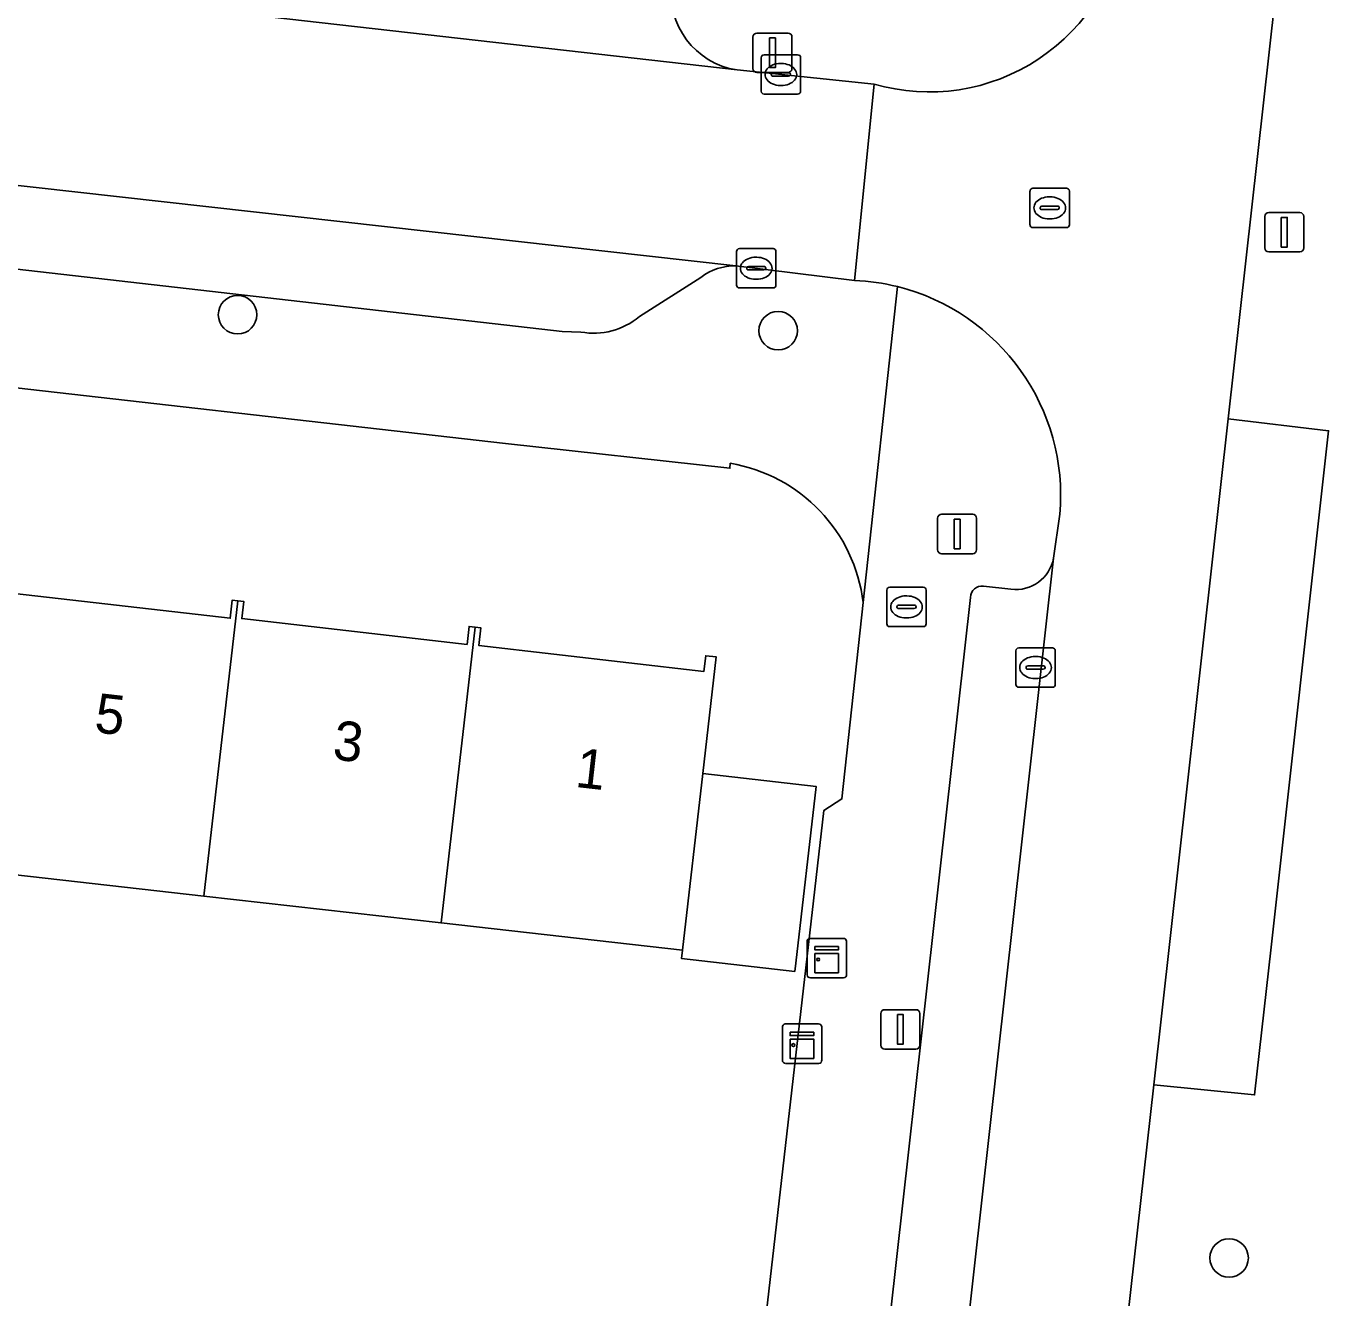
# Model space of a CAD drawing. Extents: x 161928 to 163071, y 386474 to 387428.
# Drawn here: x 162156.16 to 162189.6, y 386612.39 to 386644.64 of the extents above; entities that cross this region are included whole.
import ezdxf

# ---------------------------------------------------------------- set-up
doc = ezdxf.new("R2010")
doc.units = 0
for name, color, linetype in [('IMGEO_Berm_groen', 7, 'Continuous'), ('IMGEO_Boom', 7, 'Continuous'), ('IMGEO_Brandkraan', 7, 'Continuous'), ('IMGEO_Erf', 7, 'Continuous'), ('IMGEO_Kast', 7, 'Continuous'), ('IMGEO_Kolk', 7, 'Continuous'), ('IMGEO_Lichtmast', 7, 'Continuous'), ('IMGEO_Pand', 7, 'Continuous'), ('IMGEO_Pand_nummerreeks', 7, 'Continuous'), ('IMGEO_Parkeervlak_open', 7, 'Continuous'), ('IMGEO_Rijbaan_lokaal_open', 7, 'Continuous'), ('IMGEO_Rioolput', 7, 'Continuous'), ('IMGEO_Voetpad_open', 7, 'Continuous')]:
    doc.layers.add(name, color=color, linetype=linetype)

msp = doc.modelspace()

# ---------------------------------------------------------------- linework, layer by layer
at = {"layer": 'IMGEO_Berm_groen'}
msp.add_lwpolyline([(162189.709, 386662.217), (162189.32, 386658.663), (162186.639, 386634.684), (162189.19, 386634.379), (162187.73, 386621.281), (162187.312, 386617.53), (162184.757, 386617.783), (162181.174, 386585.88)], dxfattribs=at)
at = {"layer": 'IMGEO_Boom'}
for centre in [(162161.515, 386637.324), (162175.227, 386636.918), (162186.666, 386613.392)]:
    msp.add_circle(centre, 0.489, dxfattribs=at)
at = {"layer": 'IMGEO_Brandkraan'}
for p, q in [((162177.982, 386629.484), (162177.982, 386630.336)), ((162178.057, 386630.41), (162178.909, 386630.41)), ((162178.983, 386630.336), (162178.983, 386629.484)), ((162178.47, 386630.19), (162178.495, 386630.19)), ((162178.241, 386629.904), (162178.241, 386629.916)), ((162178.679, 386629.867), (162178.281, 386629.867)), ((162178.284, 386629.953), (162178.682, 386629.953)), ((162178.725, 386629.916), (162178.725, 386629.904)), ((162178.909, 386629.41), (162178.057, 386629.41)), ((162178.493, 386629.63), (162178.468, 386629.63))]:
    msp.add_line(p, q, dxfattribs=at)
for points in [[(162177.982, 386629.484), (162177.982, 386630.336)], [(162178.057, 386630.41), (162178.909, 386630.41)], [(162178.983, 386630.336), (162178.983, 386629.484)], [(162178.909, 386629.41), (162178.057, 386629.41)]]:
    msp.add_lwpolyline(points, dxfattribs=at)
for centre, radius, start, end in [((162178.059, 386630.334), 0.0765, 91.552, 178.448), ((162178.059, 386630.334), 0.0765, 91.552, 178.448), ((162178.907, 386630.334), 0.0765, 1.552, 88.448), ((162178.907, 386630.334), 0.0765, 1.552, 88.448), ((162178.281, 386629.913), 0.0403, 85.8775, 175.7526), ((162178.278, 386629.903), 0.0366, 178.938, 274.7102), ((162178.682, 386629.91), 0.043, 264.8664, 352.4533), ((162178.686, 386629.915), 0.0386, 1.7309, 96.639), ((162178.059, 386629.486), 0.0765, 181.552, 268.448), ((162178.059, 386629.486), 0.0765, 181.552, 268.448), ((162178.907, 386629.486), 0.0765, 271.552, 358.448), ((162178.907, 386629.486), 0.0765, 271.552, 358.448)]:
    msp.add_arc(centre, radius, start, end, dxfattribs=at)
for centre, major_axis, ratio, start_param, end_param in [((162178.469, 386629.91), (-0.387, 0.002), 0.722429, 4.712389, 7.853982), ((162178.494, 386629.91), (-0.39, 0.002), 0.717154, 1.570796, 4.712389)]:
    msp.add_ellipse(centre, major_axis=major_axis, ratio=ratio, start_param=start_param, end_param=end_param, dxfattribs=at)
at = {"layer": 'IMGEO_Erf'}
for points in [[(162174.012, 386633.555), (162174.002, 386633.43), (162168.309, 386634.058), (162124.601, 386639.029), (162121.966, 386615.861), (162125.693, 386615.447), (162129.321, 386615.04), (162133.478, 386614.574), (162133.214, 386612.225)], [(162155.563, 386630.286), (162161.329, 386629.621), (162161.382, 386630.083), (162161.525, 386630.067), (162161.671, 386630.05), (162161.621, 386629.616), (162167.335, 386628.957), (162167.388, 386629.414), (162167.54, 386629.396), (162167.688, 386629.379), (162167.637, 386628.931), (162173.345, 386628.273), (162173.391, 386628.671), (162173.656, 386628.641), (162173.316, 386625.686), (162176.189, 386625.355), (162175.673, 386620.876), (162175.648, 386620.661), (162172.775, 386620.992), (162172.799, 386621.201), (162166.676, 386621.893), (162160.662, 386622.573), (162154.617, 386623.256)], [(162176.389, 386624.747), (162176.844, 386625.037), (162177.384, 386630.02)], [(162174.405, 386607.455), (162176.389, 386624.747)]]:
    msp.add_lwpolyline(points, dxfattribs=at)
msp.add_arc((162173.329, 386629.528), 4.084, 6.9173, 80.3789, dxfattribs=at)
at = {"layer": 'IMGEO_Kast'}
for p, q in [((162175.963, 386620.576), (162175.963, 386621.417)), ((162175.963, 386621.417), (162175.963, 386620.576)), ((162176.038, 386621.501), (162176.879, 386621.501)), ((162176.879, 386621.501), (162176.038, 386621.501)), ((162176.963, 386621.426), (162176.963, 386620.585)), ((162176.963, 386620.585), (162176.963, 386621.426)), ((162176.888, 386620.501), (162176.047, 386620.501)), ((162176.047, 386620.501), (162176.888, 386620.501)), ((162175.409, 386619.329), (162176.25, 386619.329)), ((162176.25, 386619.329), (162175.409, 386619.329)), ((162175.334, 386618.404), (162175.334, 386619.245)), ((162175.334, 386619.245), (162175.334, 386618.404)), ((162176.334, 386619.254), (162176.334, 386618.413)), ((162176.334, 386618.413), (162176.334, 386619.254)), ((162176.259, 386618.329), (162175.418, 386618.329)), ((162175.418, 386618.329), (162176.259, 386618.329))]:
    msp.add_line(p, q, dxfattribs=at)
for points in [[(162176.158, 386621.291), (162176.758, 386621.291), (162176.758, 386621.206), (162176.158, 386621.206), (162176.158, 386621.291)], [(162176.158, 386621.116), (162176.758, 386621.116), (162176.758, 386620.627), (162176.158, 386620.627), (162176.158, 386621.116)], [(162175.529, 386619.119), (162176.129, 386619.119), (162176.129, 386619.034), (162175.529, 386619.034), (162175.529, 386619.119)], [(162175.529, 386618.944), (162176.129, 386618.944), (162176.129, 386618.455), (162175.529, 386618.455), (162175.529, 386618.944)]]:
    msp.add_lwpolyline(points, dxfattribs=at)
for centre in [(162176.242, 386620.965), (162175.613, 386618.793)]:
    msp.add_circle(centre, 0.0377, dxfattribs=at)
for centre, start, end in [((162176.041, 386621.423), 92.4484, 184.2845), ((162176.041, 386621.423), 92.4484, 184.2845), ((162176.885, 386621.423), 2.4484, 94.2845), ((162176.885, 386621.423), 2.4484, 94.2845), ((162176.041, 386620.579), 182.4484, 274.2845), ((162176.041, 386620.579), 182.4484, 274.2845), ((162176.885, 386620.579), 272.4484, 4.2845), ((162176.885, 386620.579), 272.4484, 4.2845), ((162175.412, 386619.251), 92.4484, 184.2845), ((162175.412, 386619.251), 92.4484, 184.2845), ((162176.256, 386619.251), 2.4484, 94.2845), ((162176.256, 386619.251), 2.4484, 94.2845), ((162175.412, 386618.407), 182.4484, 274.2845), ((162175.412, 386618.407), 182.4484, 274.2845), ((162176.256, 386618.407), 272.4484, 4.2845), ((162176.256, 386618.407), 272.4484, 4.2845)]:
    msp.add_arc(centre, 0.0779, start, end, dxfattribs=at)
at = {"layer": 'IMGEO_Kolk'}
for p, q in [((162174.795, 386642.992), (162174.795, 386643.844)), ((162174.87, 386643.918), (162175.722, 386643.918)), ((162175.283, 386643.698), (162175.308, 386643.698)), ((162175.796, 386643.844), (162175.796, 386642.992)), ((162175.054, 386643.412), (162175.054, 386643.424)), ((162175.492, 386643.375), (162175.094, 386643.375)), ((162175.097, 386643.461), (162175.495, 386643.461)), ((162175.538, 386643.424), (162175.538, 386643.412)), ((162175.306, 386643.138), (162175.281, 386643.138)), ((162175.722, 386642.918), (162174.87, 386642.918)), ((162174.245, 386639.002), (162175.097, 386639.002)), ((162174.17, 386638.076), (162174.17, 386638.928)), ((162174.658, 386638.782), (162174.683, 386638.782)), ((162175.171, 386638.928), (162175.171, 386638.076)), ((162174.429, 386638.496), (162174.429, 386638.508)), ((162174.867, 386638.459), (162174.469, 386638.459)), ((162174.472, 386638.545), (162174.87, 386638.545)), ((162174.913, 386638.508), (162174.913, 386638.496)), ((162175.097, 386638.002), (162174.245, 386638.002)), ((162174.681, 386638.222), (162174.656, 386638.222)), ((162181.256, 386627.946), (162181.256, 386628.798)), ((162181.331, 386628.872), (162182.183, 386628.872)), ((162181.744, 386628.652), (162181.769, 386628.652)), ((162182.257, 386628.798), (162182.257, 386627.946)), ((162181.515, 386628.366), (162181.515, 386628.378)), ((162181.953, 386628.329), (162181.555, 386628.329)), ((162181.558, 386628.415), (162181.956, 386628.415)), ((162181.999, 386628.378), (162181.999, 386628.366)), ((162181.767, 386628.092), (162181.742, 386628.092)), ((162182.183, 386627.872), (162181.331, 386627.872))]:
    msp.add_line(p, q, dxfattribs=at)
for points in [[(162174.795, 386642.992), (162174.795, 386643.844)], [(162174.87, 386643.918), (162175.722, 386643.918)], [(162175.796, 386643.844), (162175.796, 386642.992)], [(162175.722, 386642.918), (162174.87, 386642.918)], [(162174.245, 386639.002), (162175.097, 386639.002)], [(162174.17, 386638.076), (162174.17, 386638.928)], [(162175.171, 386638.928), (162175.171, 386638.076)], [(162175.097, 386638.002), (162174.245, 386638.002)], [(162181.256, 386627.946), (162181.256, 386628.798)], [(162181.331, 386628.872), (162182.183, 386628.872)], [(162182.257, 386628.798), (162182.257, 386627.946)], [(162182.183, 386627.872), (162181.331, 386627.872)]]:
    msp.add_lwpolyline(points, dxfattribs=at)
for centre, radius, start, end in [((162174.872, 386643.842), 0.0765, 91.552, 178.448), ((162174.872, 386643.842), 0.0765, 91.552, 178.448), ((162175.72, 386643.842), 0.0765, 1.552, 88.448), ((162175.72, 386643.842), 0.0765, 1.552, 88.448), ((162175.094, 386643.421), 0.0403, 85.8775, 175.7526), ((162175.091, 386643.411), 0.0366, 178.938, 274.7102), ((162175.495, 386643.418), 0.043, 264.8664, 352.4533), ((162175.499, 386643.423), 0.0386, 1.7309, 96.639), ((162174.872, 386642.994), 0.0765, 181.552, 268.448), ((162174.872, 386642.994), 0.0765, 181.552, 268.448), ((162175.72, 386642.994), 0.0765, 271.552, 358.448), ((162175.72, 386642.994), 0.0765, 271.552, 358.448), ((162174.247, 386638.926), 0.0765, 91.552, 178.448), ((162174.247, 386638.926), 0.0765, 91.552, 178.448), ((162175.095, 386638.926), 0.0765, 1.552, 88.448), ((162175.095, 386638.926), 0.0765, 1.552, 88.448), ((162174.469, 386638.505), 0.0403, 85.8775, 175.7526), ((162174.466, 386638.495), 0.0366, 178.938, 274.7102), ((162174.87, 386638.502), 0.043, 264.8664, 352.4533), ((162174.874, 386638.507), 0.0386, 1.7309, 96.639), ((162174.247, 386638.078), 0.0765, 181.552, 268.448), ((162174.247, 386638.078), 0.0765, 181.552, 268.448), ((162175.095, 386638.078), 0.0765, 271.552, 358.448), ((162175.095, 386638.078), 0.0765, 271.552, 358.448), ((162181.333, 386628.796), 0.0765, 91.552, 178.448), ((162181.333, 386628.796), 0.0765, 91.552, 178.448), ((162182.181, 386628.796), 0.0765, 1.552, 88.448), ((162182.181, 386628.796), 0.0765, 1.552, 88.448), ((162181.555, 386628.375), 0.0403, 85.8775, 175.7526), ((162181.552, 386628.365), 0.0366, 178.938, 274.7102), ((162181.956, 386628.372), 0.043, 264.8664, 352.4533), ((162181.96, 386628.377), 0.0386, 1.7309, 96.639), ((162181.333, 386627.948), 0.0765, 181.552, 268.448), ((162181.333, 386627.948), 0.0765, 181.552, 268.448), ((162182.181, 386627.948), 0.0765, 271.552, 358.448), ((162182.181, 386627.948), 0.0765, 271.552, 358.448)]:
    msp.add_arc(centre, radius, start, end, dxfattribs=at)
for centre, major_axis, ratio, start_param, end_param in [((162175.282, 386643.418), (-0.387, 0.002), 0.722429, 4.712389, 7.853982), ((162175.307, 386643.418), (-0.39, 0.002), 0.717154, 1.570796, 4.712389), ((162174.657, 386638.502), (-0.387, 0.002), 0.722429, 4.712389, 7.853982), ((162174.682, 386638.502), (-0.39, 0.002), 0.717154, 1.570796, 4.712389), ((162181.743, 386628.372), (-0.387, 0.002), 0.722429, 4.712389, 7.853982), ((162181.768, 386628.372), (-0.39, 0.002), 0.717154, 1.570796, 4.712389)]:
    msp.add_ellipse(centre, major_axis=major_axis, ratio=ratio, start_param=start_param, end_param=end_param, dxfattribs=at)
at = {"layer": 'IMGEO_Lichtmast'}
for p, q in [((162174.588, 386643.569), (162174.588, 386644.369)), ((162174.588, 386644.369), (162174.588, 386643.569)), ((162174.688, 386644.469), (162175.478, 386644.469)), ((162175.478, 386644.469), (162174.688, 386644.469)), ((162175.578, 386644.369), (162175.578, 386643.569)), ((162175.578, 386643.569), (162175.578, 386644.369)), ((162175.478, 386643.469), (162174.688, 386643.469)), ((162174.688, 386643.469), (162175.478, 386643.469)), ((162187.57, 386639.016), (162187.57, 386639.816)), ((162187.57, 386639.816), (162187.57, 386639.016)), ((162187.67, 386639.916), (162188.46, 386639.916)), ((162188.46, 386639.916), (162187.67, 386639.916)), ((162188.56, 386639.816), (162188.56, 386639.016)), ((162188.56, 386639.016), (162188.56, 386639.816)), ((162188.46, 386638.916), (162187.67, 386638.916)), ((162187.67, 386638.916), (162188.46, 386638.916)), ((162179.272, 386631.36), (162179.272, 386632.16)), ((162179.272, 386632.16), (162179.272, 386631.36)), ((162179.372, 386632.26), (162180.162, 386632.26)), ((162180.162, 386632.26), (162179.372, 386632.26)), ((162180.262, 386632.16), (162180.262, 386631.36)), ((162180.262, 386631.36), (162180.262, 386632.16)), ((162180.162, 386631.26), (162179.372, 386631.26)), ((162179.372, 386631.26), (162180.162, 386631.26)), ((162177.931, 386619.692), (162178.721, 386619.692)), ((162178.721, 386619.692), (162177.931, 386619.692)), ((162177.831, 386618.792), (162177.831, 386619.592)), ((162177.831, 386619.592), (162177.831, 386618.792)), ((162178.821, 386619.592), (162178.821, 386618.792)), ((162178.821, 386618.792), (162178.821, 386619.592)), ((162178.721, 386618.692), (162177.931, 386618.692)), ((162177.931, 386618.692), (162178.721, 386618.692))]:
    msp.add_line(p, q, dxfattribs=at)
for points in [[(162175.008, 386644.344), (162175.158, 386644.344), (162175.158, 386643.594), (162175.008, 386643.594), (162175.008, 386644.344)], [(162187.99, 386639.791), (162188.14, 386639.791), (162188.14, 386639.041), (162187.99, 386639.041), (162187.99, 386639.791)], [(162179.692, 386632.135), (162179.842, 386632.135), (162179.842, 386631.385), (162179.692, 386631.385), (162179.692, 386632.135)], [(162178.251, 386619.567), (162178.401, 386619.567), (162178.401, 386618.817), (162178.251, 386618.817), (162178.251, 386619.567)]]:
    msp.add_lwpolyline(points, dxfattribs=at)
for centre, start, end in [((162174.688, 386644.369), 90, 180), ((162174.688, 386644.369), 90, 180), ((162175.478, 386644.369), 0, 90), ((162175.478, 386644.369), 360, 90), ((162174.688, 386643.569), 180, 270), ((162174.688, 386643.569), 180, 270), ((162175.478, 386643.569), 270, 0), ((162175.478, 386643.569), 270, 0), ((162187.67, 386639.816), 90, 180), ((162187.67, 386639.816), 90, 180), ((162188.46, 386639.816), 0, 90), ((162188.46, 386639.816), 360, 90), ((162187.67, 386639.016), 180, 270), ((162187.67, 386639.016), 180, 270), ((162188.46, 386639.016), 270, 0), ((162188.46, 386639.016), 270, 0), ((162179.372, 386632.16), 90, 180), ((162179.372, 386632.16), 90, 180), ((162180.162, 386632.16), 0, 90), ((162180.162, 386632.16), 360, 90), ((162179.372, 386631.36), 180, 270), ((162179.372, 386631.36), 180, 270), ((162180.162, 386631.36), 270, 0), ((162180.162, 386631.36), 270, 0), ((162177.931, 386619.592), 90, 180), ((162177.931, 386619.592), 90, 180), ((162178.721, 386619.592), 0, 90), ((162178.721, 386619.592), 360, 90), ((162177.931, 386618.792), 180, 270), ((162177.931, 386618.792), 180, 270), ((162178.721, 386618.792), 270, 0), ((162178.721, 386618.792), 270, 0)]:
    msp.add_arc(centre, 0.1, start, end, dxfattribs=at)
at = {"layer": 'IMGEO_Pand'}
for points in [[(162161.525, 386630.067), (162161.382, 386630.083), (162161.329, 386629.621), (162155.563, 386630.286), (162155.614, 386630.724), (162155.478, 386630.739), (162154.617, 386623.256), (162160.662, 386622.573)], [(162160.662, 386622.573), (162166.676, 386621.893), (162167.54, 386629.396), (162167.388, 386629.414), (162167.335, 386628.957), (162161.621, 386629.616), (162161.671, 386630.05), (162161.525, 386630.067)], [(162173.316, 386625.686), (162173.656, 386628.641), (162173.391, 386628.671), (162173.345, 386628.273), (162167.637, 386628.931), (162167.688, 386629.379), (162167.54, 386629.396), (162166.676, 386621.893), (162172.799, 386621.201)], [(162173.316, 386625.686), (162172.799, 386621.201), (162172.775, 386620.992), (162175.648, 386620.661), (162175.673, 386620.876), (162176.189, 386625.355)]]:
    msp.add_lwpolyline(points, close=True, dxfattribs=at)
at = {"layer": 'IMGEO_Parkeervlak_open'}
for points in [[(162127.319, 386643.804), (162127.088, 386641.777), (162169.752, 386636.9), (162170.223, 386636.883)], [(162174.153, 386638.563), (162127.319, 386643.804)], [(162171.708, 386637.274), (162173.267, 386638.27)], [(162175.325, 386569.478), (162182.213, 386631.15)], [(162181.131, 386630.359), (162180.434, 386630.439)], [(162180.106, 386630.152), (162173.549, 386571.44)]]:
    msp.add_lwpolyline(points, dxfattribs=at)
msp.add_lwpolyline([(162187.73, 386621.281), (162189.19, 386634.379), (162186.639, 386634.684), (162184.757, 386617.783), (162187.312, 386617.53)], close=True, dxfattribs=at)
for centre, radius, start, end in [((162174.133, 386637.139), 1.425, 89.1794, 127.4186), ((162170.543, 386638.682), 1.827, 259.8979, 309.6044), ((162181.252, 386631.329), 0.978, 262.8969, 349.4408), ((162180.398, 386630.149), 0.292, 82.995, 179.3769)]:
    msp.add_arc(centre, radius, start, end, dxfattribs=at)
at = {"layer": 'IMGEO_Rijbaan_lokaal_open'}
for points in [[(162181.174, 386585.88), (162184.757, 386617.783), (162186.639, 386634.684), (162189.32, 386658.663), (162185.35, 386659.121), (162185.117, 386656.967), (162184.282, 386649.581), (162184.043, 386647.418)], [(162177.659, 386643.176), (162177.166, 386638.193)], [(162182.371, 386632.259), (162182.213, 386631.15), (162175.325, 386569.478)]]:
    msp.add_lwpolyline(points, dxfattribs=at)
msp.add_lwpolyline([(162137.297, 386647.725), (162127.886, 386648.779), (162127.319, 386643.804), (162174.153, 386638.563), (162177.166, 386638.193), (162177.659, 386643.176), (162174.184, 386643.534)], close=True, dxfattribs=at)
for centre, radius, start, end in [((162179.063, 386647.988), 5.013, 253.7355, 353.4705), ((162176.936, 386632.768), 5.43, 75.9747, 87.5731), ((162176.934, 386632.739), 5.458, 354.95, 76.0277)]:
    msp.add_arc(centre, radius, start, end, dxfattribs=at)
at = {"layer": 'IMGEO_Rioolput'}
for p, q in [((162181.615, 386639.607), (162181.615, 386640.459)), ((162181.69, 386640.533), (162182.542, 386640.533)), ((162182.616, 386640.459), (162182.616, 386639.607)), ((162181.874, 386640.027), (162181.874, 386640.039)), ((162181.917, 386640.076), (162182.315, 386640.076)), ((162182.103, 386640.313), (162182.128, 386640.313)), ((162182.358, 386640.039), (162182.358, 386640.027)), ((162182.312, 386639.99), (162181.914, 386639.99)), ((162182.126, 386639.753), (162182.101, 386639.753)), ((162182.542, 386639.533), (162181.69, 386639.533))]:
    msp.add_line(p, q, dxfattribs=at)
for points in [[(162181.615, 386639.607), (162181.615, 386640.459)], [(162181.69, 386640.533), (162182.542, 386640.533)], [(162182.616, 386640.459), (162182.616, 386639.607)], [(162182.542, 386639.533), (162181.69, 386639.533)]]:
    msp.add_lwpolyline(points, dxfattribs=at)
for centre, radius, start, end in [((162181.692, 386640.457), 0.0765, 91.552, 178.448), ((162181.692, 386640.457), 0.0765, 91.552, 178.448), ((162182.54, 386640.457), 0.0765, 1.552, 88.448), ((162182.54, 386640.457), 0.0765, 1.552, 88.448), ((162181.914, 386640.036), 0.0403, 85.8775, 175.7526), ((162181.911, 386640.026), 0.0366, 178.938, 274.7102), ((162182.315, 386640.033), 0.043, 264.8664, 352.4533), ((162182.319, 386640.038), 0.0386, 1.7309, 96.639), ((162181.692, 386639.609), 0.0765, 181.552, 268.448), ((162181.692, 386639.609), 0.0765, 181.552, 268.448), ((162182.54, 386639.609), 0.0765, 271.552, 358.448), ((162182.54, 386639.609), 0.0765, 271.552, 358.448)]:
    msp.add_arc(centre, radius, start, end, dxfattribs=at)
for centre, major_axis, ratio, start_param, end_param in [((162182.102, 386640.033), (-0.387, 0.002), 0.722429, 4.712389, 7.853982), ((162182.127, 386640.033), (-0.39, 0.002), 0.717154, 1.570796, 4.712389)]:
    msp.add_ellipse(centre, major_axis=major_axis, ratio=ratio, start_param=start_param, end_param=end_param, dxfattribs=at)
at = {"layer": 'IMGEO_Voetpad_open'}
for points in [[(162075.194, 386649.565), (162074.703, 386644.498), (162083.251, 386643.731), (162123.254, 386639.182), (162124.601, 386639.029), (162168.309, 386634.058), (162174.002, 386633.43), (162174.012, 386633.555)], [(162137.297, 386647.725), (162174.184, 386643.534)], [(162170.223, 386636.883), (162169.752, 386636.9), (162127.088, 386641.777), (162124.305, 386642.089), (162080.121, 386647.031)], [(162174.184, 386643.534), (162177.659, 386643.176)], [(162177.166, 386638.193), (162174.153, 386638.563)], [(162178.252, 386638.036), (162177.384, 386630.02), (162176.844, 386625.037), (162176.389, 386624.747), (162174.405, 386607.455), (162174.401, 386607.421), (162174.537, 386607.366), (162174.366, 386605.829), (162168.995, 386557.594), (162168.981, 386557.465), (162168.883, 386557.469), (162168.714, 386555.921), (162168.149, 386550.32)], [(162173.267, 386638.27), (162171.708, 386637.274)], [(162177.384, 386630.02), (162178.252, 386638.036)], [(162182.213, 386631.15), (162182.371, 386632.259)], [(162180.434, 386630.439), (162181.131, 386630.359)], [(162173.549, 386571.44), (162180.106, 386630.152)]]:
    msp.add_lwpolyline(points, dxfattribs=at)
for centre, radius, start, end in [((162179.063, 386647.988), 5.013, 253.7355, 353.4705), ((162174.479, 386645.482), 1.97, 172.2543, 261.3943), ((162174.479, 386645.482), 1.97, 172.2543, 261.3943), ((162174.133, 386637.139), 1.425, 89.1794, 127.4186), ((162176.936, 386632.768), 5.43, 75.9747, 87.5731), ((162176.934, 386632.739), 5.458, 354.95, 76.0277), ((162170.543, 386638.682), 1.827, 259.8979, 309.6044), ((162173.329, 386629.528), 4.084, 6.9173, 80.3789), ((162181.252, 386631.329), 0.978, 262.8969, 349.4408), ((162180.398, 386630.149), 0.292, 82.995, 179.3769)]:
    msp.add_arc(centre, radius, start, end, dxfattribs=at)

# ---------------------------------------------------------------- texts
at = {"layer": 'IMGEO_Pand_nummerreeks'}
for s, rotation, p in [('5', 353.5056, (162157.859, 386626.734)), ('3', 353.5056, (162163.902, 386626.046)), ('1', 353.5084, (162170.057, 386625.346))]:
    msp.add_text(s, height=1, rotation=rotation, dxfattribs=at).set_placement(p)

doc.saveas('drawing.dxf')
